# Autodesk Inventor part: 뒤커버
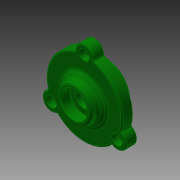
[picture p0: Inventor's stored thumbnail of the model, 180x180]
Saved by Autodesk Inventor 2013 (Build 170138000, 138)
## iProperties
Created: 2016-05
Part Number: 뒤커버
Document SubType Name: Modeling
Designer: mduedu
Density: 2.71 g/cm^3
Material: 알루미늄 6061
Author: mduedu
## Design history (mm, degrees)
sketch "스케치1"
  geometry: C1 r 19 at (0, 0); C2 r 29 at (0, 0); 1 further point
  constraints: 2 centre point, 2 coincident
  dimensions: "d33" = 58 diameter of C2; "d34" = 38 diameter of C1
extrude "돌출1" new body sketch "스케치1" distance "d0" = 8; taper "d1" = 0 deg
extrude "돌출2" join sketch "스케치1" distance "d2" = 8; taper "d3" = 0 deg; dims "d35" = 9, "d36" = 0
sketch "스케치5"
  geometry: L1 (-29, 8)-(29, 8) reference; L2 (0, 0)-(0, 15); L3 (-29, 0)-(29, 0) reference; L4 (17.5, 8)-(0, 8); A1 r 25.375 centre (0, -10.375) between (17.5, 8) and (0, 15)
  constraints: 4 end point, 3 point on line, 2 point on circle, 1 centre point, 1 midpoint, 1 perpendicular
  dimensions: "d37" = 17.5 distance from line of L2 L4.start; "d39" = 7 distance from line of L1 L2.end
revolve "회전2" sketch "스케치5" stored, may be unused: angle "d40" = 90 deg
node "작업 평면1"
sketch "스케치6"
  geometry: C1 r 13.5 at (0, 0); 1 further point
  constraints: 1 centre point, 1 coincident
  dimensions: "d42" = 27 diameter of C1
extrude "돌출4" join sketch "스케치6" stored distance "d43" = 10; taper "d44" = 0 deg
sketch "스케치4"
  geometry: L1 (0, -9)-(0, 16); L2 (-15, -9)-(-15, 0); L3 (-15, 0)-(-10, 0); L4 (-10, 0)-(-10, 3); L5 (-10, 3)-(-6, 3); L6 (-6, 3)-(-6, 8.6); L7 (-6, 8.6)-(-10, 8.6); L8 (-10, 8.6)-(-10, 16); L9 (19, -9)-(-19, -9) reference; L10 (-13.5, 16)-(13.5, 16) reference; 1 further point
  constraints: 16 end point, 6 parallel, 3 point on line, 2 midpoint, 1 perpendicular, 1 vertical
  dimensions: "d15" = 30 diameter of L2 L1; "d16" = 20 diameter of L8 L1; "d18" = 9 distance of L2.start L2.end; "d19" = 3 distance of L3.end L4.end; "d20" = 20 diameter of L4 L1; "d21" = 12 diameter of L6 L1; "d45" = 7.4 distance of L7.end L8.end
revolve "회전1" sketch "스케치4" stored, may be unused: angle "d22" = 90 deg
fillet "모깎기2" dims "d23" = 3
fillet "모깎기3" dims "d24" = 0.3
chamfer "모따기2" distance "d46" = 1; stored, may be unused: second distance "d47" = 2, angle "d48" = 45 deg
fillet "모깎기4" dims "d49" = 3
fillet "모깎기5" dims "d50" = 2
sketch "스케치7"
  geometry: C1 r 7 at (0, 29); 2 further points
  constraints: 3 vertical alignment, 1 centre point, 2 other
  dimensions: "d54" = 14 diameter of C1
extrude "돌출5" join sketch "스케치7" stored distance "d55" = 10; taper "d56" = 0 deg
fillet "모깎기6" dims "d57" = 1
fillet "모깎기7" dims "d61" = 1
sketch "스케치8" dims "d62" = 58 (derived)
  geometry: C1 r 18.661 at (0, 0) reference; A1 r 2 centre (-8, 28.914) between (-7.466, 26.986) and (-6, 28.935) reference; A2 r 28 centre (0, 0) between (-7.466, 26.986) and (-27.104, -7.027) reference; A3 r 2 centre (-29.04, -7.529) between (-28.059, -9.272) and (-27.104, -7.027) reference; A4 r 6 centre (-25.115, -14.5) between (-28.059, -9.272) and (-22.059, -19.664) reference; A5 r 2 centre (-21.04, -21.385) between (-19.638, -19.959) and (-22.059, -19.664) reference; A6 r 28 centre (0, 0) between (-19.638, -19.959) and (19.638, -19.959) reference; A7 r 2 centre (21.04, -21.385) between (22.059, -19.664) and (19.638, -19.959) reference; A8 r 6 centre (25.115, -14.5) between (22.059, -19.664) and (28.059, -9.272) reference; A9 r 2 centre (29.04, -7.529) between (27.104, -7.027) and (28.059, -9.272) reference; A10 r 28 centre (0, 0) between (27.104, -7.027) and (7.466, 26.986) reference; A11 r 2 centre (8, 28.914) between (6, 28.935) and (7.466, 26.986) reference; A12 r 6 centre (0, 29) between (6, 28.935) and (-6, 28.935) reference; 4 further points
  constraints: 2 coincident, 1 vertical alignment, 6 other
  dimensions: "d65" = 360 deg dimension on A2.centre point (0, 29) (derived)
sketch "스케치9"
  geometry: A1 r 7 centre (0, 29) between (7, 28.925) and (-7, 28.925) reference; A2 r 7 centre (25.115, -14.5) between (21.55, -20.524) and (28.549, -8.4) reference; A3 r 7 centre (-25.115, -14.5) between (-28.549, -8.4) and (-21.55, -20.524) reference; 3 further points
  constraints: 3 coincident
hole "구멍2" sketch "스케치9" at (-25.115, -14.5), (25.115, -14.5), (0, 29) diameter "d67" = 4.5; stored, may be unused: countersink angle "d71" = 90 deg, drill point angle "d73" = 0 deg; dims "d68" = 6, "d69" = 8, "d70" = 4.6, "d72" = 8
chamfer "모따기3" distance "d76" = 0.7; stored, may be unused: second distance "d77" = 2, angle "d78" = 30 deg
node "솔리드1"
pattern_circular "원형 패턴1" dims angle "d59" = 360 deg
other parameters: "d41" = 8
